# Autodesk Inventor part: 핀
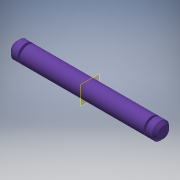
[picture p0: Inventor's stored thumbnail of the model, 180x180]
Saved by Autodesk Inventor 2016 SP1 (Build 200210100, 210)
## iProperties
Created: 2019-02
Part Number: 핀
Material: 스테인리스강
Document SubType Name: Modeling
Designer: mduedu
Density: 1 g/cm^3
Appearance: 보라색
Author: mduedu
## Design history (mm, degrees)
sketch "스케치1"
  geometry: L1 (-26, 0)-(26, 0); L2 (26, 0)-(26, 3); L3 (26, 3)-(-26, 3); L4 (-26, 3)-(-26, 0); L5 (-22.7, 3)-(-22, 3); L6 (-22, 3)-(-22, 2); L7 (-22, 2)-(-22.7, 2); L8 (-22.7, 2)-(-22.7, 3); L9 (0, 0)-(0, 3); L10 (22.7, 3)-(22, 3); L11 (22, 3)-(22, 2); L12 (22, 2)-(22.7, 2); L13 (22.7, 2)-(22.7, 3); 1 further point
  constraints: 26 end point, 4 parallel, 4 symmetric about line, 2 horizontal, 2 midpoint, 2 perpendicular, 1 coincident, 1 point on line
  dimensions: "d0" = 52 distance between parallel lines of L2 L4; "d2" = 6 diameter of L3 L1; "d3" = 4 diameter of L7 L1; "d4" = 44 distance between parallel lines of L11 L6; "d5" = 0.7 distance between parallel lines of L6 L8
revolve "회전1" sketch "스케치1" stored, may be unused: angle "d6" = 90 deg
chamfer "모따기1" distance "d7" = 1; stored, may be unused: second distance "d8" = 2, angle "d9" = 45 deg
node "작업 평면1"
node "솔리드1"
